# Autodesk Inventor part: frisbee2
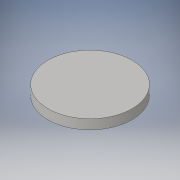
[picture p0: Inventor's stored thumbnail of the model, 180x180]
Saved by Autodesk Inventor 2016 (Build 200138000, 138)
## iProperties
Created: 2020-02
Part Number: frisbee2
Material: Generic
Document SubType Name: Modeling
Designer: merlin
Density: 1 g/cm^3
Appearance: Default
Author: merlin
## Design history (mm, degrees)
sketch "Sketch1"
  geometry: C1 r 88.9 at (0, 0); 1 further point
  constraints: 1 centre point, 1 coincident
  dimensions: "d0" = 177.8 diameter of C1
extrude "Extrusion1" new body sketch "Sketch1" distance "d1" = 20.32; taper "d2" = 0 deg
body "Solid1"
